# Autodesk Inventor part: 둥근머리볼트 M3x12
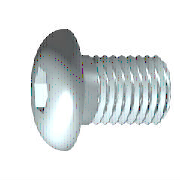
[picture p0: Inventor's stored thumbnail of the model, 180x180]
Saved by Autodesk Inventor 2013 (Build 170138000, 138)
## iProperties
IsCustomPart: 0
Created: 2012-02
Part Number: 둥근머리볼트 M3x12
Material: 강철
Description: 6각 소켓 버튼 머리 나사 - 제품 등급 A
Document SubType Name: Modeling
Standard: ISO 7380
Designer: mduedu
Standard Revision: Third edition 2004-01-15
Standards Organization: ISO
Language: ko-KR
Size Designation: M3 x 12
Categories: <MemberInstance><Categories><Category DisplayName="조임쇠" InternalName="e4da775c-781d-43d5-af7c-5136215cf5a6" Mnemonic="FSTN"><Category DisplayName="볼트" InternalN
Density: 7.85 g/cm^3
Author: mduedu
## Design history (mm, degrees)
sketch "스케치1"
  geometry: L1 (0.057, 0)-(12, 0); L2 (12, 0)-(12, 1.5); L3 (12, 1.5)-(1, 1.5); L4 (1, 1.5)-(0.693, 1.5); L5 (0.693, 1.5)-(0, 1.5); L6 (0, 1.5)-(0, 2.85); L7 (0, 2.85)-(-1.65, 2.85); L8 (-1.65, 2.85)-(-1.65, 1.155); L9 (-1.65, 1.155)-(-0.61, 1.155); L10 (-0.61, 1.155)-(0.057, 0); L11 (-4.38, 0)-(14.73, 0) reference; L12 (0, -0.57)-(0, 3.42) reference; L13 (1, 1.5)-(0, 1.5)
  constraints: 22 end point, 6 parallel, 2 collinear, 2 perpendicular, 1 horizontal, 1 point on line
  dimensions: "d1" = 11 distance from line of L3.end L2 (= GEL); "d2" = 0.30683 distance of L4.end L3.end (computed from GAL); "d3" = 1.65 distance between parallel lines of L8 L6 (= KOH); "d4" = 1.04 distance of L8.end L9.end (= INTI); "d5" = 60 deg angle of L10 L1; "d6" = 3 diameter of L3 L1 (= GD); "d7" = 3 diameter of L5 L1 (= BDM); "d8" = 2.3094 diameter of L9 L1 (= 1.1547 x SW); "d9" = 5.7 diameter of L7 L1 (= KOD); "d26" = 12 distance between parallel lines of L12 L2 (= NLG)
revolve "본체" sketch "스케치1" stored, may be unused: angle "d10" = 90 deg
sketch "스케치2"
  geometry: L1 (0, -3.99)-(0, 3.99) reference; L2 (-3.99, 0)-(3.99, 0) reference; L3 (1.155, 0)-(0.577, -1); L4 (0.577, -1)-(-0.577, -1); L5 (-0.577, -1)-(-1.155, 0); L6 (-1.155, 0)-(-0.577, 1); L7 (-0.577, 1)-(0.577, 1); L8 (0.577, 1)-(1.155, 0); 2 further points
  constraints: 12 end point, 1 coincident, 1 horizontal alignment, 1 point on line, 12 other
extrude "슬롯" join sketch "스케치2" stored distance "d11" = 10; taper "d12" = 0 deg
workplane "Work Plane1"
body "Solid1"
fillet "모깎기1" dims "d17" = 1.45 (= RR)
feature "스레드" dims "d13" = 11 (= GEL), "d14" = 0
chamfer "모따기1" distance "d15" = 0.30673 (= -0.5 x SPD + 0.5 x GD); stored, may be unused: second distance "d16" = 0.30673 (= GUL), angle "d27" = 45 deg
fillet "모깎기2" dims "d30" = 0.1 (= R)
other parameters: "GD" = 3 (= NND) [user parameter; used in 2 equation terms], "NLG" = 12 [user parameter; used in 1 equation term], "GEL" = 11 [user parameter; used in 2 equation terms], "KOD" = 5.7 [user parameter; used in 1 equation term], "KOH" = 1.65 [user parameter; used in 1 equation term], "INTI" = 1.04 [user parameter; used in 1 equation term], "GAL" = 0.30673 (= 0.61345 x PTC) [user parameter; used in 1 equation term], "GUL" = 0.30673 (= 0.61345 x PTC) [user parameter; used in 1 equation term], "BDM" = 3 (= NND) [user parameter; used in 1 equation term], "SW" = 2 [user parameter; used in 1 equation term], "RR" = 1.45 [user parameter; used in 1 equation term], "SPD" = 2.38655 (= NND - 1.2269 x PTC) [user parameter; used in 1 equation term], "d19" = 0, "d28" = 0, "d29" = 0, "R" = 0.1 [user parameter; used in 1 equation term], "TOA" = 30 deg [user parameter], "GD1" = 2.38655 (= THREADDIA - 1.2269 x PTC) [user parameter], "THREADDIA" = 3 [user parameter; used in 1 equation term], "PTC" = 0.5 [user parameter; used in 5 equation terms], "NND" = 3 [user parameter; used in 3 equation terms], "KOH1" = 0.2 [user parameter], "E0" = 2.31 [user parameter]
